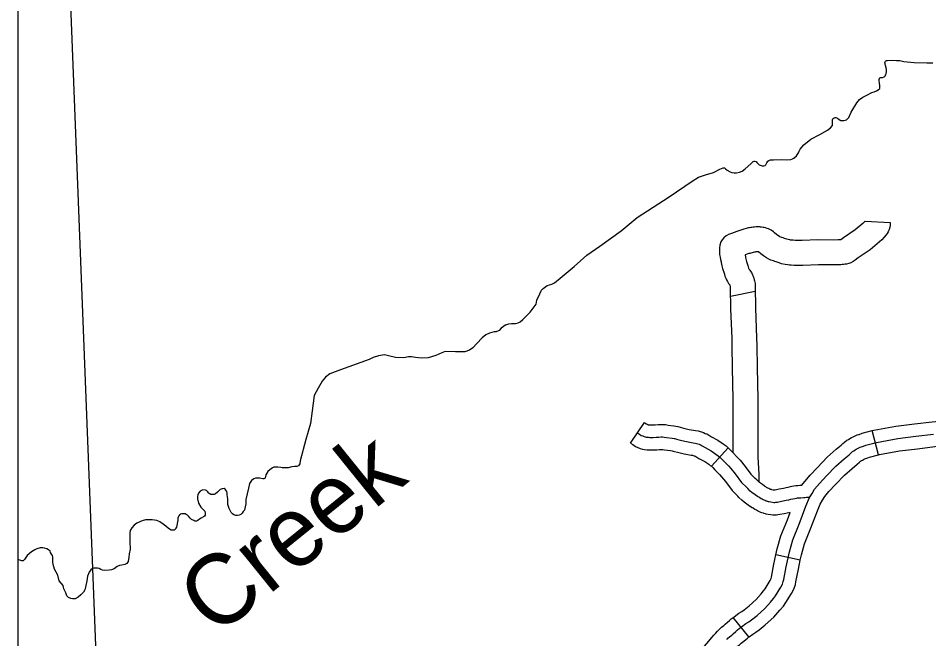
# Model space of a CAD drawing. Extents: x 1720274 to 1751788, y 372074 to 391887.
# Drawn here: x 1729991 to 1730856, y 378002 to 378591 of the extents above; entities that cross this region are included whole.
import ezdxf

# ---------------------------------------------------------------- set-up
doc = ezdxf.new("R2010")
doc.units = 0
for name, color, linetype in [('Level 32', 7, 'Continuous'), ('Level 35', 7, 'Continuous'), ('Level 45', 7, 'Continuous'), ('Level 5', 7, 'Continuous'), ('R_Draft', 7, 'Continuous')]:
    doc.layers.add(name, color=color, linetype=linetype)

msp = doc.modelspace()

# ---------------------------------------------------------------- linework, layer by layer
at = {"layer": 'Level 32'}
for p, q in [((1730572.99, 378187.62), (1730586.04, 378207.4)), ((1730808.6, 378176.74), (1730802.76, 378199.7)), ((1730649.76, 378165.75), (1730665.58, 378183.4)), ((1730734.29, 378076.51), (1730711.14, 378081.57)), ((1730685.29, 378003.7), (1730670.35, 378022.1))]:
    msp.add_line(p, q, dxfattribs=at)
for points in [[(1730802.76, 378199.7), (1730804.34, 378200.11), (1730825.2, 378204.02), (1730842.83, 378206.03), (1730859.51, 378207.98), (1730878.42, 378209.95), (1730886.1, 378210.67)], [(1730586.04, 378207.4), (1730587.77, 378206.26), (1730588.7, 378205.68), (1730589.02, 378205.53), (1730589.55, 378205.33), (1730589.61, 378205.32), (1730590.96, 378205.15), (1730591.65, 378205.1), (1730594.14, 378205.07), (1730596.39, 378205.21), (1730599.12, 378205.39), (1730601.77, 378205.52), (1730603.79, 378205.52), (1730606.16, 378205.35), (1730608.65, 378205), (1730613.98, 378204.16), (1730616.04, 378203.94), (1730617.83, 378203.59), (1730619.92, 378203), (1730624.46, 378201.74), (1730628.52, 378200.84), (1730634.53, 378199.8), (1730637.15, 378199.35), (1730642.11, 378197.84), (1730643.98, 378197.05), (1730645.32, 378196.47), (1730646.91, 378195.55), (1730649.71, 378193.89), (1730655.78, 378190.53), (1730660.86, 378187.17), (1730663.7, 378185.08), (1730665.58, 378183.4)], [(1730579.52, 378197.51), (1730581.35, 378196.3), (1730583.14, 378195.17), (1730584.47, 378194.59), (1730585.85, 378194.05), (1730586.89, 378193.76), (1730587.89, 378193.59), (1730589.84, 378193.34), (1730591.22, 378193.26), (1730594.43, 378193.22), (1730597.13, 378193.38), (1730599.8, 378193.55), (1730602.07, 378193.67), (1730603.36, 378193.67), (1730604.91, 378193.55), (1730606.92, 378193.28), (1730612.42, 378192.41), (1730614.26, 378192.21), (1730615.09, 378192.05), (1730616.73, 378191.59), (1730621.59, 378190.24), (1730626.22, 378189.22), (1730632.52, 378188.12), (1730634.42, 378187.8), (1730638.08, 378186.68), (1730639.33, 378186.15), (1730639.98, 378185.87), (1730640.93, 378185.33), (1730643.81, 378183.61), (1730649.63, 378180.39), (1730654.08, 378177.44), (1730656.22, 378175.87), (1730658.13, 378174.16), (1730659.5, 378172.82), (1730661.53, 378170.67), (1730665.87, 378166.25), (1730668.35, 378163.76), (1730672.49, 378158.51), (1730678.42, 378150.54), (1730683.23, 378145.84)], [(1730735.52, 378147.58), (1730743.61, 378157.33), (1730750.56, 378164.79), (1730759.79, 378174.46), (1730768.34, 378181.91), (1730773.08, 378185.81), (1730774.87, 378187.36), (1730776.46, 378188.84), (1730778.66, 378190.47), (1730780.18, 378191.39), (1730781.43, 378192.17), (1730783.01, 378193.04), (1730784.56, 378193.9), (1730786.46, 378194.83), (1730788.34, 378195.52), (1730789.48, 378195.9), (1730790.1, 378196.13), (1730792.97, 378197.21), (1730802.76, 378199.7)], [(1730743.16, 378136.27), (1730745.45, 378139.79), (1730747.91, 378143.95), (1730752.52, 378149.5), (1730759.18, 378156.66), (1730767.99, 378165.88), (1730775.99, 378172.87), (1730780.73, 378176.76), (1730782.79, 378178.55), (1730784.04, 378179.72), (1730785.25, 378180.61), (1730786.37, 378181.28), (1730787.44, 378181.95), (1730788.74, 378182.67), (1730790.04, 378183.39), (1730791.12, 378183.92), (1730792.26, 378184.34), (1730793.43, 378184.73), (1730794.26, 378185.04), (1730796.53, 378185.89), (1730806.89, 378188.53), (1730826.96, 378192.29), (1730844.2, 378194.26), (1730860.81, 378196.2)], [(1730572.99, 378187.62), (1730574.93, 378186.34), (1730577.58, 378184.67), (1730579.92, 378183.65), (1730582.06, 378182.8), (1730584.31, 378182.17), (1730586.16, 378181.87), (1730588.73, 378181.54), (1730590.78, 378181.41), (1730594.71, 378181.36), (1730597.88, 378181.56), (1730600.48, 378181.72), (1730602.37, 378181.82), (1730602.93, 378181.82), (1730603.67, 378181.76), (1730605.18, 378181.55), (1730610.86, 378180.66), (1730612.41, 378180.49), (1730613.55, 378180.18), (1730618.72, 378178.74), (1730623.92, 378177.59), (1730630.52, 378176.44), (1730631.69, 378176.24), (1730634.04, 378175.52), (1730634.65, 378175.27), (1730634.94, 378175.1), (1730637.91, 378173.34), (1730643.48, 378170.24), (1730647.3, 378167.72), (1730648.74, 378166.66), (1730649.76, 378165.75)], [(1730808.61, 378176.74), (1730809.45, 378176.95), (1730828.73, 378180.57), (1730845.56, 378182.49), (1730862.11, 378184.43), (1730880.76, 378186.36), (1730889.32, 378187.21)], [(1730665.58, 378183.4), (1730666.24, 378182.81), (1730667.96, 378181.12), (1730670.07, 378178.89), (1730674.29, 378174.58), (1730677.23, 378171.64), (1730681.89, 378165.71), (1730687.37, 378158.36), (1730691.51, 378154.32)], [(1730753.09, 378129.81), (1730755.52, 378133.54), (1730757.63, 378137.11), (1730761.42, 378141.68), (1730767.8, 378148.53), (1730776.18, 378157.31), (1730783.65, 378163.82), (1730788.39, 378167.71), (1730790.72, 378169.74), (1730791.63, 378170.59), (1730791.84, 378170.75), (1730792.56, 378171.18), (1730793.45, 378171.74), (1730794.47, 378172.3), (1730795.51, 378172.87), (1730795.79, 378173.01), (1730796.18, 378173.15), (1730797.39, 378173.56), (1730798.42, 378173.94), (1730800.08, 378174.57), (1730808.6, 378176.74)], [(1730649.76, 378165.75), (1730650.03, 378165.51), (1730651.05, 378164.51), (1730652.99, 378162.46), (1730657.44, 378157.91), (1730659.47, 378155.88), (1730663.08, 378151.3), (1730669.47, 378142.71), (1730674.94, 378137.37)], [(1730735.52, 378147.58), (1730733.93, 378147.45), (1730732.08, 378147.35), (1730730, 378147.25), (1730728.08, 378146.95), (1730726.38, 378146.59), (1730724.54, 378146.16), (1730722.49, 378145.7), (1730720.69, 378145.32), (1730718.31, 378144.79), (1730714.08, 378143.92), (1730710.42, 378143.16), (1730709.84, 378143.06), (1730709.69, 378143.04), (1730709.3, 378143.08), (1730708.48, 378143.21), (1730707.34, 378143.49), (1730706.79, 378143.62), (1730706.19, 378143.78), (1730705.88, 378143.86), (1730705.85, 378143.88), (1730705.55, 378144), (1730705.16, 378144.18), (1730704.29, 378144.59), (1730703.48, 378145.02), (1730702.91, 378145.31), (1730702.29, 378145.71), (1730701.52, 378146.21), (1730700.34, 378147.01), (1730698.23, 378148.44), (1730695.52, 378150.34), (1730694.76, 378150.99), (1730692.97, 378152.8), (1730691.51, 378154.32)], [(1730743.16, 378136.27), (1730740.32, 378136.06), (1730738.53, 378135.9), (1730737.21, 378135.82), (1730734.71, 378135.63), (1730732.71, 378135.52), (1730731.2, 378135.44), (1730730.21, 378135.29), (1730728.97, 378135.02), (1730727.19, 378134.61), (1730725, 378134.12), (1730723.18, 378133.74), (1730720.8, 378133.21), (1730716.48, 378132.31), (1730712.67, 378131.53), (1730711.44, 378131.31), (1730710.66, 378131.23), (1730709.84, 378131.17), (1730709.04, 378131.2), (1730707.83, 378131.32), (1730706.13, 378131.58), (1730704.62, 378131.96), (1730703.94, 378132.11), (1730703.11, 378132.34), (1730702.54, 378132.49), (1730701.82, 378132.72), (1730701.37, 378132.91), (1730700.8, 378133.13), (1730700.08, 378133.47), (1730698.98, 378134), (1730698.06, 378134.48), (1730697, 378135.01), (1730695.83, 378135.78), (1730694.96, 378136.34), (1730693.69, 378137.2), (1730691.51, 378138.68), (1730688.25, 378140.97), (1730686.7, 378142.29), (1730684.48, 378144.53), (1730683.23, 378145.84)], [(1730664.35, 378001.18), (1730665.43, 378002.37), (1730666.96, 378003.79), (1730669.07, 378005.44), (1730670.47, 378006.63), (1730672.95, 378008.76), (1730674.68, 378010.25), (1730676.31, 378011.68), (1730678.41, 378013.38), (1730682.55, 378016.27), (1730685.5, 378018.15), (1730687.93, 378019.9), (1730693.38, 378024.1), (1730700.69, 378030.8), (1730705.96, 378036.7), (1730708.84, 378040.13), (1730710.73, 378042.86), (1730715.85, 378051.08), (1730717.33, 378053.69), (1730718.1, 378056.2), (1730718.48, 378058.22), (1730720.81, 378070.32), (1730723.91, 378084.52), (1730727.17, 378096), (1730733.05, 378110.69), (1730739.62, 378127.97), (1730743.16, 378136.27)], [(1730724.64, 378121.9), (1730718.88, 378120.71), (1730714.91, 378119.89), (1730713.05, 378119.56), (1730711.71, 378119.43), (1730710.05, 378119.29), (1730708.21, 378119.38), (1730706.37, 378119.55), (1730703.78, 378119.96), (1730701.89, 378120.43), (1730701.09, 378120.61), (1730700.02, 378120.9), (1730699.22, 378121.11), (1730697.75, 378121.58), (1730696.88, 378121.94), (1730696.05, 378122.27), (1730695, 378122.77), (1730693.67, 378123.4), (1730692.64, 378123.94), (1730691.09, 378124.72), (1730689.37, 378125.84), (1730688.41, 378126.47), (1730687.04, 378127.39), (1730684.78, 378128.92), (1730680.98, 378131.6), (1730678.64, 378133.59), (1730675.98, 378136.27), (1730674.94, 378137.37)], [(1730734.29, 378076.51), (1730735.41, 378081.64), (1730738.4, 378092.17), (1730744.09, 378106.38), (1730750.61, 378123.54), (1730753.09, 378129.81)], [(1730711.14, 378081.57), (1730712.41, 378087.4), (1730715.93, 378099.83), (1730722.01, 378114.99), (1730724.64, 378121.9)], [(1730670.35, 378022.1), (1730671.27, 378022.85), (1730675.97, 378026.13), (1730678.85, 378027.96), (1730680.85, 378029.4), (1730685.74, 378033.18), (1730692.25, 378039.14), (1730697, 378044.46), (1730699.42, 378047.33), (1730700.83, 378049.36), (1730705.66, 378057.14), (1730706.38, 378058.4), (1730706.58, 378059.05), (1730706.85, 378060.45), (1730709.2, 378072.7), (1730711.14, 378081.57)], [(1730685.29, 378003.7), (1730685.55, 378003.91), (1730689.12, 378006.41), (1730692.15, 378008.33), (1730695.02, 378010.41), (1730701.01, 378015.03), (1730709.13, 378022.46), (1730714.92, 378028.94), (1730718.27, 378032.93), (1730720.64, 378036.35), (1730726.04, 378045.02), (1730728.28, 378048.97), (1730729.61, 378053.34), (1730730.12, 378055.98), (1730732.42, 378067.94), (1730734.29, 378076.51)], [(1730612.76, 377958.39), (1730614.54, 377960.66), (1730631.36, 377981.57), (1730645.38, 377997.57), (1730652.21, 378005.23), (1730653.71, 378007.08), (1730655.57, 378009.13), (1730656.99, 378010.71), (1730659.27, 378012.82), (1730661.59, 378014.64), (1730662.79, 378015.65), (1730665.21, 378017.73), (1730666.91, 378019.2), (1730668.68, 378020.74), (1730670.35, 378022.1)], [(1730631.43, 377943.79), (1730633.11, 377945.93), (1730649.51, 377966.32), (1730663.14, 377981.87), (1730670.26, 377989.87), (1730671.71, 377991.65), (1730673.14, 377993.23), (1730673.87, 377994.04), (1730674.65, 377994.76), (1730676.54, 377996.24), (1730678.16, 377997.61), (1730680.69, 377999.78), (1730682.45, 378001.3), (1730683.95, 378002.61), (1730685.29, 378003.7)]]:
    msp.add_lwpolyline(points, dxfattribs=at)
at = {"layer": 'Level 35'}
for points in [[(1730804.51, 378521.49), (1730806.75, 378522.41), (1730808.46, 378523.33), (1730809.78, 378524.65), (1730810.02, 378525.85), (1730809.96, 378526.81), (1730809.79, 378527.94), (1730809.57, 378528.79), (1730809.51, 378529.58), (1730809.45, 378530.48), (1730809.4, 378531.56), (1730809.34, 378532.63), (1730809.34, 378533.65), (1730809.45, 378534.05), (1730809.74, 378534.5), (1730810.02, 378534.84), (1730810.58, 378535.06), (1730811.15, 378535.12), (1730812.45, 378535.18), (1730813.97, 378535.69), (1730814.54, 378536.02), (1730814.93, 378536.65), (1730815.5, 378537.83), (1730816.01, 378539.08), (1730816.23, 378540.55), (1730816.18, 378542.81), (1730815.93, 378544.44), (1730815.17, 378546.71), (1730814.82, 378548.05), (1730814.77, 378548.98), (1730814.86, 378550.14), (1730815.17, 378550.67), (1730815.57, 378550.98), (1730816.33, 378551.29), (1730817.13, 378551.38), (1730820.73, 378551.6), (1730825.66, 378551.43), (1730828.77, 378551.25), (1730832.64, 378550.36), (1730842.42, 378549.47), (1730854.46, 378548.98), (1730860.2, 378549.11)], [(1730454.47, 378300.28), (1730457.19, 378301.23), (1730459.56, 378301.49), (1730461.53, 378301.49), (1730463.64, 378301.49), (1730466.14, 378302.02), (1730467.98, 378302.94), (1730470.61, 378305.18), (1730477.59, 378312.29), (1730483.25, 378319.94), (1730483.64, 378323.49), (1730486.54, 378329.68), (1730488.25, 378332.98), (1730489.83, 378334.56), (1730493.64, 378337.59), (1730497.99, 378338.77), (1730500.62, 378340.09), (1730506.02, 378344.44), (1730519.18, 378355.64), (1730531.42, 378366.31), (1730543.66, 378374.87), (1730563.93, 378389.62), (1730579.32, 378402.01), (1730609.73, 378421.76), (1730631.58, 378436.78), (1730637.5, 378440.47), (1730645, 378443.11), (1730648.68, 378444.03), (1730651.71, 378444.95), (1730657.77, 378447.98), (1730659.48, 378448.77), (1730661.06, 378449.3), (1730662.11, 378449.3), (1730663.29, 378448.38), (1730664.87, 378447.06), (1730667.51, 378445.61), (1730669.22, 378444.82), (1730671.45, 378444.55), (1730673.69, 378444.55), (1730676.59, 378445.08), (1730679.09, 378446.27), (1730681.85, 378448.24), (1730687.38, 378453.12), (1730689.62, 378455.23), (1730690.41, 378455.75), (1730691.2, 378455.75), (1730692.25, 378455.49), (1730693.04, 378454.43), (1730695.14, 378452.2), (1730696.07, 378451.8), (1730698.17, 378451.27), (1730699.62, 378451.14), (1730700.94, 378451.54), (1730701.59, 378452.33), (1730702.51, 378454.04), (1730703.44, 378455.62), (1730704.23, 378456.28), (1730705.15, 378456.67), (1730705.8, 378456.94), (1730706.73, 378457.07), (1730708.7, 378457.07), (1730716.47, 378457.33), (1730720.81, 378457.07), (1730725.28, 378457.33), (1730726.99, 378457.73), (1730728.18, 378458.52), (1730730.81, 378460.76), (1730732.52, 378463.52), (1730733.05, 378465.24), (1730734.1, 378467.21), (1730737.52, 378471.3), (1730744.37, 378476.57), (1730752.92, 378481.04), (1730760.29, 378485.13), (1730763.06, 378487.37), (1730764.77, 378489.48), (1730764.9, 378491.71), (1730764.9, 378492.77), (1730764.9, 378494.22), (1730764.9, 378495.14), (1730765.16, 378495.8), (1730765.56, 378496.33), (1730766.35, 378496.72), (1730767.4, 378497.25), (1730768.19, 378497.25), (1730769.51, 378496.59), (1730771.22, 378495.4), (1730772.93, 378494.35), (1730774.11, 378494.35), (1730775.82, 378494.35), (1730777.01, 378494.61), (1730778.19, 378495.01), (1730779.11, 378495.8), (1730780.43, 378497.25), (1730782.54, 378502.12), (1730788.19, 378511.08), (1730790.7, 378514.24), (1730793.72, 378516.48), (1730797.67, 378518.46), (1730802.15, 378520.83), (1730804.51, 378521.49)], [(1730454.47, 378300.28), (1730450.03, 378297.13), (1730447.99, 378294.72), (1730445.21, 378293.61), (1730443.36, 378293.42), (1730438.91, 378292.31), (1730435.21, 378290.64), (1730431.69, 378287.68), (1730426.87, 378282.48), (1730422.8, 378278.22), (1730419.84, 378276.18), (1730415.39, 378274.51), (1730406.5, 378274.51), (1730396.5, 378274.7), (1730393.35, 378273.59), (1730387.61, 378270.99), (1730380.38, 378268.77), (1730374.09, 378268.4), (1730368.53, 378269.14), (1730364.64, 378269.88), (1730361.86, 378269.88)], [(1730361.86, 378269.88), (1730357.23, 378268.95), (1730349.27, 378269.14), (1730342.78, 378270.62), (1730339.08, 378271.55), (1730333.34, 378270.62), (1730328.15, 378269.14), (1730324.45, 378267.1), (1730297.03, 378257.27), (1730286.85, 378253.56), (1730282.96, 378250.41), (1730279.62, 378246.52), (1730275.73, 378239.85), (1730272.21, 378233.17), (1730270.18, 378218.53), (1730268.51, 378206.48), (1730264.06, 378191.09), (1730258.69, 378171.07), (1730258.51, 378168.1), (1730257.21, 378166.06), (1730255.54, 378165.5), (1730253.32, 378165.5), (1730250.73, 378165.32), (1730247.39, 378164.21), (1730244.8, 378164.21), (1730241.65, 378164.21), (1730240.35, 378164.76), (1730237.58, 378164.95), (1730235.72, 378164.95), (1730233.87, 378164.95), (1730232.39, 378164.21), (1730229.8, 378162.54), (1730227.94, 378160.68), (1730226.28, 378157.72), (1730225.46, 378154.96), (1730225.11, 378154.25), (1730224.31, 378153.89), (1730223.42, 378153.98), (1730220.39, 378154.43), (1730218.43, 378154.61), (1730216.3, 378154.52), (1730214.61, 378153.8), (1730212.65, 378152.29), (1730210.6, 378149.35), (1730209.71, 378145.08), (1730207.04, 378134.21), (1730207.22, 378130.2), (1730206.51, 378127.26), (1730205.89, 378124.14), (1730204.73, 378122.72), (1730203.57, 378121.21), (1730202.33, 378119.96), (1730200.73, 378119.25), (1730199.3, 378119.07), (1730197.7, 378119.16), (1730195.74, 378119.69), (1730194.59, 378120.49), (1730193.25, 378122.01), (1730191.29, 378125.66), (1730190.14, 378129.49), (1730189.96, 378132.07), (1730189.87, 378135.01), (1730189.51, 378138.66), (1730189.51, 378140.36), (1730189.07, 378141.69), (1730188.18, 378143.21), (1730187.56, 378144.01), (1730186.67, 378144.54), (1730184.62, 378144.45), (1730182.75, 378143.65), (1730180.17, 378141.25), (1730178.12, 378139.73), (1730176.97, 378139.02), (1730175.1, 378138.93), (1730173.94, 378139.11), (1730172.16, 378139.82), (1730171.63, 378140.62), (1730170.83, 378141.51), (1730169.58, 378142.76), (1730168.87, 378143.21), (1730166.29, 378143.29), (1730163.8, 378142.23), (1730162.1, 378140.27), (1730161.48, 378138.66), (1730161.3, 378137.06), (1730161.04, 378134.83), (1730162.15, 378130.89), (1730164.26, 378126.89), (1730168.02, 378123), (1730168.61, 378120.88), (1730168.5, 378119.36), (1730167.79, 378118.53), (1730166.73, 378117.71), (1730164.62, 378116.53), (1730163.09, 378115.59), (1730161.56, 378114.3), (1730160.15, 378113.71), (1730158.5, 378113.71), (1730157.56, 378114.18), (1730155.56, 378115.12), (1730154.15, 378116.65)], [(1730154.15, 378116.65), (1730152.62, 378118.3), (1730151.57, 378119.24), (1730150.51, 378119.94), (1730149.33, 378120.53), (1730147.45, 378120.77), (1730146.27, 378120.77), (1730145.1, 378120.3), (1730144.28, 378119.94), (1730143.45, 378118.77), (1730142.86, 378117.47), (1730142.51, 378116.53), (1730142.39, 378114.53), (1730141.22, 378108.06), (1730140.63, 378107), (1730139.81, 378105.82), (1730138.87, 378105.23), (1730137.69, 378105.23), (1730136.16, 378105.23), (1730133.58, 378106.65), (1730131.11, 378108.76), (1730128.4, 378110.65), (1730125.23, 378113), (1730122.64, 378114.18), (1730118.17, 378115), (1730115.12, 378115), (1730111.83, 378114.77), (1730108.53, 378114.06), (1730103.48, 378111.71), (1730100.89, 378109.71), (1730098.78, 378107.35), (1730097.25, 378104.76), (1730096.78, 378102.65), (1730096.78, 378099.23), (1730096.78, 378094.06), (1730097.01, 378087.11), (1730096.31, 378082.76), (1730095.84, 378079.46), (1730095.13, 378075.34), (1730093.96, 378073.58), (1730092.07, 378072.4), (1730089.25, 378071.93), (1730086.9, 378071.46), (1730084.9, 378070.52), (1730081.85, 378068.28), (1730079.49, 378067.34), (1730077.03, 378066.99), (1730072.44, 378066.64), (1730070.91, 378066.99), (1730069.15, 378067.7), (1730067.62, 378068.52), (1730066.21, 378069.11), (1730064.21, 378069.11), (1730062.56, 378069.11), (1730060.92, 378068.28), (1730059.74, 378067.34), (1730058.21, 378065.34), (1730057.39, 378063.46), (1730056.69, 378061.46), (1730055.86, 378056.99), (1730054.69, 378050.87), (1730053.98, 378048.4), (1730052.81, 378046.16), (1730050.34, 378043.57), (1730047.75, 378041.57), (1730044.81, 378039.92), (1730042.34, 378039.81), (1730040.58, 378040.04), (1730038.58, 378041.1), (1730037.05, 378042.75), (1730035.99, 378045.57), (1730034.11, 378049.34), (1730033.29, 378052.63), (1730029.76, 378056.87), (1730028.47, 378062.4), (1730025.29, 378068.17), (1730023.88, 378072.52), (1730023.77, 378075.11), (1730023.77, 378077.7), (1730023.65, 378079.58), (1730023.3, 378080.88), (1730022.47, 378082.41), (1730021.53, 378083.82), (1730020.94, 378084.99), (1730019.42, 378086.29), (1730018, 378087.35), (1730015.65, 378087.94), (1730014.13, 378088.17), (1730011.66, 378088.29), (1730008.25, 378087.23), (1730006.48, 378086.52), (1730003.19, 378084.52), (1729999.19, 378080.88), (1729996.61, 378077.11), (1729995.43, 378076.05), (1729994.02, 378075.82), (1729991.43, 378076.76), (1729990.7, 378077.21)]]:
    msp.add_lwpolyline(points, dxfattribs=at)
at = {"layer": 'Level 45'}
for p, q in [((1730796.01, 378398.82), (1730819.71, 378397.36)), ((1730667.88, 378327.52), (1730691.52, 378332.28))]:
    msp.add_line(p, q, dxfattribs=at)
for points in [[(1730736.03, 378380.29), (1730732.74, 378380.26), (1730729.55, 378380.37), (1730727.43, 378380.52), (1730725.8, 378380.65), (1730724.96, 378380.72), (1730724.23, 378380.82), (1730722.6, 378381.18), (1730721.46, 378381.54), (1730719.18, 378382.32), (1730717.98, 378382.76), (1730716.67, 378383.23), (1730714.89, 378383.86), (1730714.73, 378383.92), (1730714.5, 378384.06), (1730712.78, 378385.19), (1730711.69, 378385.99), (1730709.9, 378387.56), (1730708.75, 378388.56), (1730706.72, 378390.02), (1730705.3, 378390.73), (1730704.08, 378391.31), (1730702.78, 378391.79), (1730701.26, 378392.29), (1730699.94, 378392.54), (1730698.96, 378392.76), (1730697.32, 378393), (1730696.32, 378393.05), (1730695.34, 378393.15), (1730694.18, 378393.21), (1730693.32, 378393.21), (1730692.19, 378393.21), (1730690.71, 378393.1), (1730689.35, 378392.97), (1730688.19, 378392.8), (1730687.21, 378392.67), (1730686.13, 378392.47), (1730684.9, 378392.23), (1730683.67, 378391.88), (1730682.76, 378391.56), (1730680.74, 378391.06), (1730678.81, 378390.59), (1730673.84, 378388.88), (1730668.9, 378386.98), (1730666.06, 378385.89), (1730663.75, 378384.61), (1730661.65, 378382.92), (1730660.08, 378381.04), (1730658.69, 378378.96), (1730657.66, 378375.86), (1730657.35, 378373.33), (1730657.35, 378371.81), (1730657.35, 378369.79), (1730657.59, 378367.03), (1730658.01, 378364.36), (1730658.46, 378362.24), (1730658.92, 378359.9), (1730659.01, 378359.47)], [(1730796.01, 378398.82), (1730795.01, 378397.78), (1730793.78, 378396.6), (1730786.45, 378390.5), (1730775.35, 378382.99), (1730772.84, 378381.05), (1730772.73, 378381.03), (1730772.38, 378380.99), (1730771.98, 378380.95), (1730771.63, 378380.93), (1730770.19, 378380.89), (1730765.68, 378380.75), (1730751.07, 378380.82), (1730736.14, 378380.29), (1730736.03, 378380.29)], [(1730819.71, 378397.36), (1730819.71, 378396.07), (1730819.63, 378394.57), (1730819.4, 378392.96), (1730818.86, 378390.79), (1730818.3, 378389.56), (1730817.89, 378388.59), (1730817.03, 378387.1), (1730816.05, 378385.68), (1730813.99, 378383.34), (1730811.75, 378380.99), (1730809.55, 378378.9), (1730800.71, 378371.54), (1730789.26, 378363.78), (1730786.47, 378361.63), (1730784.41, 378360.2), (1730782.36, 378359.14), (1730780.3, 378358.32), (1730778.33, 378357.91), (1730776.83, 378357.67), (1730775.83, 378357.54), (1730774.9, 378357.42), (1730773.95, 378357.34), (1730772.95, 378357.25), (1730770.87, 378357.2), (1730765.98, 378357.05), (1730751.43, 378357.12), (1730736.66, 378356.59), (1730736.23, 378356.59)], [(1730736.23, 378356.59), (1730732.42, 378356.56), (1730728.3, 378356.7), (1730725.68, 378356.89), (1730723.94, 378357.02), (1730722.28, 378357.15), (1730719.92, 378357.51), (1730716.47, 378358.27), (1730714.06, 378359.03), (1730711.33, 378359.96), (1730709.97, 378360.45), (1730708.7, 378360.91), (1730706.4, 378361.72), (1730704.32, 378362.58), (1730702.12, 378363.83), (1730699.23, 378365.73), (1730696.82, 378367.51), (1730694.66, 378369.4), (1730694.61, 378369.41), (1730693.54, 378369.51), (1730693.52, 378369.51), (1730693.32, 378369.51), (1730693.07, 378369.51), (1730692.77, 378369.49), (1730692.16, 378369.43), (1730691.41, 378369.32), (1730690.94, 378369.26), (1730690.61, 378369.2), (1730689.51, 378368.82), (1730686.4, 378368.04), (1730685.47, 378367.82), (1730681.95, 378366.6), (1730681.77, 378366.53), (1730682.16, 378364.56), (1730682.24, 378364.15)], [(1730659.01, 378359.47), (1730659.67, 378356.18), (1730660.34, 378353.67), (1730661.76, 378349.41), (1730662.13, 378348.23), (1730662.19, 378347.9), (1730662.59, 378346.43), (1730663.05, 378345.25), (1730663.36, 378344.44), (1730664.05, 378342.92), (1730664.98, 378341.32), (1730665.74, 378340.22), (1730666.17, 378339.58), (1730666.61, 378338.96), (1730666.91, 378338.55), (1730667.04, 378338.36), (1730667.08, 378338.29), (1730667.15, 378338.14), (1730667.22, 378337.99), (1730667.27, 378337.85), (1730667.38, 378337.54), (1730667.42, 378337.42), (1730667.55, 378336.98), (1730667.68, 378336.6), (1730667.72, 378336.44), (1730667.76, 378335.66), (1730668.06, 378315.26), (1730669.09, 378287.2), (1730669.21, 378280.04)], [(1730682.24, 378364.15), (1730682.76, 378361.59), (1730683.05, 378360.49), (1730684.34, 378356.63), (1730685.15, 378353.97), (1730685.2, 378353.74), (1730685.32, 378353.56), (1730685.63, 378353.11), (1730685.79, 378352.88), (1730686.26, 378352.25), (1730686.96, 378351.22), (1730687.48, 378350.36), (1730687.85, 378349.73), (1730688.39, 378348.72), (1730688.89, 378347.57), (1730689.16, 378346.95), (1730689.49, 378346.09), (1730689.72, 378345.46), (1730689.95, 378344.8), (1730690.15, 378344.13), (1730690.35, 378343.52), (1730690.54, 378342.85), (1730690.83, 378341.88), (1730691.06, 378340.73), (1730691.27, 378339.49), (1730691.33, 378338.55), (1730691.37, 378338.07), (1730691.46, 378336.48), (1730691.76, 378315.87), (1730692.78, 378287.84), (1730692.91, 378280.44)], [(1730669.21, 378280.04), (1730669.57, 378259.31), (1730670.23, 378229.42), (1730670.05, 378205.58), (1730670.1, 378196.76)], [(1730692.91, 378280.44), (1730693.27, 378259.77), (1730693.93, 378229.59), (1730693.75, 378205.55), (1730693.8, 378196.89)], [(1730670.1, 378196.76), (1730670.17, 378182.63), (1730670.2, 378178.76)], [(1730693.8, 378196.89), (1730693.87, 378182.78), (1730693.93, 378174.39), (1730694.83, 378158.31), (1730694.98, 378150.72)]]:
    msp.add_lwpolyline(points, dxfattribs=at)
at = {"layer": 'Level 5'}
msp.add_lwpolyline([(1730035.65, 378725.82), (1730066.15, 377946.63)], dxfattribs=at)
at = {"layer": 'R_Draft'}
msp.add_lwpolyline([(1729990.7, 381816.11), (1741847.55, 381816.11), (1741847.55, 374371.32), (1729990.7, 374371.32)], close=True, dxfattribs=at)

# ---------------------------------------------------------------- texts
at = {"layer": 'Level 35'}
msp.add_text('Creek', height=66.739, rotation=38.94103, dxfattribs=at).set_placement((1730178.17, 378002.29))

doc.saveas('drawing.dxf')
